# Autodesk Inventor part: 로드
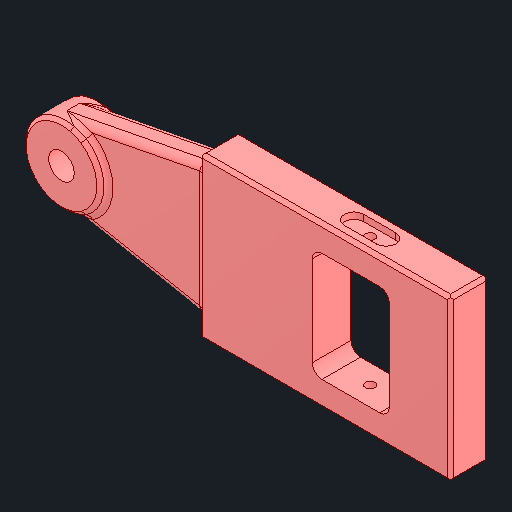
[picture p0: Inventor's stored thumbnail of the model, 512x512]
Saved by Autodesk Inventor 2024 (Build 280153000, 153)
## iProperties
Created: 2025-02
Part Number: 로드
Material: 강철, 탄소
Document SubType Name: Modeling
Designer: kh_501
Density: 7.85 g/cm^3
Appearance: 기본값
Author: jhkim
Sending System: Autodesk Inventor 2025
Preprocessor: ST-DEVELOPER v20
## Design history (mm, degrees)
node "로드1"
node "솔리드2"
node "솔리드1"
